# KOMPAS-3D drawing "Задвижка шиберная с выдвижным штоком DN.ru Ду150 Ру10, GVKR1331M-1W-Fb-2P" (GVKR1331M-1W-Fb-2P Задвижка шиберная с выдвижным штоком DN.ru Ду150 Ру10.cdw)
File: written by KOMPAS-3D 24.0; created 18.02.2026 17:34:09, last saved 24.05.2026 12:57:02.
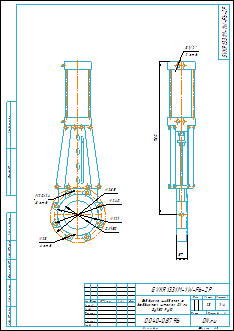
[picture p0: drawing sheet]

Document properties: Автор: R2D2; Форматы листов документа: A3; Полное имя файла: GVKR1331M-1W-Fb-2P Задвижка шиберная с выдвижным штоком DN.ru Ду150 Ру10.m3d; Масса: 23; Наименование: Задвижка шиберная с выдвижным штоком DN.ru Ду150 Ру10; Количество листов документа: 1; Примечание: D040-08796

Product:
- Part/product: Задвижка шиберная с выдвижным штоком DN.ru Ду150 Ру10  | designation GVKR1331M-1W-Fb-2P
    Масса: 23
    Раздел спецификации: Прочие изделия
    Примечание: D040-08796

Views: Вид 1, Спереди, Проекционный вид 2
Referenced files in E:\Работа\Зайцев\GVKR1331N-2W-Fb-S Задвижка шиберная с выдвижным штоком DN.ru Ду50-300 Ру10\DN50\: GVKR1331N-2W-Fb-S Задвижка шиберная DN.ru Ду50 Ру10.m3d
Referenced files in E:\Работа\Зайцев\GVKR1331M-1W-Fb-2P Задвижка шиберная с выдвижным штоком DN.ru Ду50-300 Ру16-10-6 с пневмоприводом\исходные материалы\DN150\DN150\: GVKR1331M-1W-Fb-2P Задвижка шиберная с выдвижным штоком DN.ru Ду150 Ру10.m3d
Referenced files in E:\Работа\Зайцев\Для компаса\: чертеж DN.ru А3.cdt
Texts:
  GVKR1331M-1W-Fb-2P
  чертеж DN.ru А3.cdt
  Задвижка шиберная с
  выдвижным штоком DN.ru
  Ду150 Ру10
  Задвижка шиберная с выдвижным штоком DN.ru Ду150 Ру10
  GVKR1331M-1W-Fb-2P Задвижка шиберная с выдвижным штоком DN.ru Ду150 Ру10
Dimensions and other numbers on the sheet: 0; 3; 2; 4; 20; 8 отв.; 23; 4 отв.; 285; 211; 240; 150; 2 отв.; 57; 780; 1:4; 1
